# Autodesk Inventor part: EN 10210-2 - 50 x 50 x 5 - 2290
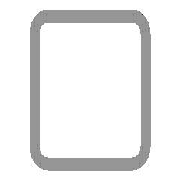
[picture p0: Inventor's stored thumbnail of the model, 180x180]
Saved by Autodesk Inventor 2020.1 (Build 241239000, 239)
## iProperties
_CCFamilyMember: 16
_CCFamilyDisplayName: DIN EN 10210-2 (USAS B17.1 quadratisch) - Rohrleitung — In Klammern angegebene Größen wurden aufgehoben
_FrameMemberDoc: Frame Member File
_Version: 15.0.0
_GetPNFromCC: 1
Created: 2019-01
Part Number: EN 10210-2 - 50 x 50 x 5 - 2290
Material: Stahl, weich
Description: Rohrleitung
Document SubType Name: Modeling
Standard: DIN
Designer: lutzd
Standard Revision: 2006-07
Standards Organization: DIN
Language: de-DE
Size Designation: 50 x 50 x 5
Categories: <MemberInstance><Categories><Category DisplayName="Profile" InternalName="089c4875-fa83-4c05-b084-43b9cc11f5ed" Mnemonic="GRDR"><CategoryParameter DisplayName="
Stock Number: 50 x 50 x 5
Mass: 15696.6 g
Surface Area: 7770.03 cm^2
Volume: 1999.57 cm^3
Density: 7.85 g/cm^3
Appearance: Halbpoliert
G_W: 50,000 mm
G_H: 50,000 mm
DocNumber: ADSK-014211
Folder: .
Dimensions: 50x50x2290 mm
Mass: 15,697 kg
+7FF69B3D-4323-48E8-BDE5-F7D3A1571190+SCHNITTDETAIL2: Schnittwinkel 90,00 grd
+7EC38CFC-9E25-4539-966B-40220C97C23E+SCHNITTDETAIL3: Schnittwinkel 90,00 grd
G_L: 2290,000 mm
IsCustomPart: 1
Title: Profil-Bauteil
Author: lutzd
Revision Number: -
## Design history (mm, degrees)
node "Startebene"
node "Endebene"
sketch "Skizze"
  geometry: L1 (-25, -17.5)-(-25, 17.5); L2 (-17.5, 25)-(17.5, 25); L3 (25, 17.5)-(25, -17.5); L4 (17.5, -25)-(-17.5, -25); L5 (-15, 20)-(15, 20); L6 (20, 15)-(20, -15); L7 (15, -20)-(-15, -20); L8 (-20, -15)-(-20, 15); L9 (0, 37.175)-(0, -37.175) reference; L10 (-37.175, 0)-(37.175, 0) reference; A1 r 7.5 centre (-17.5, -17.5) between (-25, -17.5) and (-17.5, -25); A2 r 7.5 centre (-17.5, 17.5) between (-17.5, 25) and (-25, 17.5); A3 r 7.5 centre (17.5, 17.5) between (25, 17.5) and (17.5, 25); A4 r 7.5 centre (17.5, -17.5) between (17.5, -25) and (25, -17.5); A5 r 5 centre (-15, -15) between (-20, -15) and (-15, -20); A6 r 5 centre (-15, 15) between (-15, 20) and (-20, 15); A7 r 5 centre (15, 15) between (20, 15) and (15, 20); A8 r 5 centre (15, -15) between (15, -20) and (20, -15)
  constraints: 16 end point, 16 point on circle, 16 tangent, 8 centre point, 6 equal radius, 4 parallel, 2 perpendicular, 2 other
  dimensions: "d7" = 7.5 radius of A1 (= G_IR); "d10" = 50 distance between parallel lines of L2 L4 (= G_H); "d11" = 50 distance between parallel lines of L1 L3 (= G_W); "d12" = 5 distance between parallel lines of L3 L6 (= G_T); "d15" = 25 distance between parallel lines of L2 L10 (= 0.5 x d10); "d16" = 25 distance between parallel lines of L9 L3 (= 0.5 x d11); "d19" = 5 radius of A5 (= G_T); "d20" = 5 distance between parallel lines of L4 L7 (= G_T)
extrude "Körper" new body sketch "Skizze" stored distance "d3" = 2290 (= G_L); taper "d4" = 0 deg
node "Driven Length"
  sketch "Sketch3"
    geometry: L1 (0, 0)-(10, 0) reference
    constraints: 2 end point, 1 horizontal
  workplane "Work Plane3"
  sketch "Sketch4"
    geometry: L1 (-2, 35)-(12, 35) reference; L2 (-2, 2325)-(12, 2325) reference
    dimensions: "d18" = 2290 distance between parallel lines of L1 L2 (derived)
workplane "Arbeitsebene5"
feature "Trennen2"
workplane "Arbeitsebene6"
feature "Trennen3"
body "Solid1"
other parameters: "G_W" = 50 [user parameter; used in 1 equation term], "G_H" = 50 [user parameter; used in 1 equation term], "G_T" = 5 [user parameter; used in 3 equation terms], "G_IR" = 7.5 [user parameter; used in 1 equation term], "G_L" = 2290 (= d18) [user parameter; used in 1 equation term], "G_OFFSET_START" = -35 [user parameter; used in 1 equation term], "d13" = 35 (= -G_OFFSET_START), "d14" = 2325 (= G_OFFSET_END + B_L), "B_L" = 2225 [user parameter; used in 1 equation term], "d17" = 90 deg
